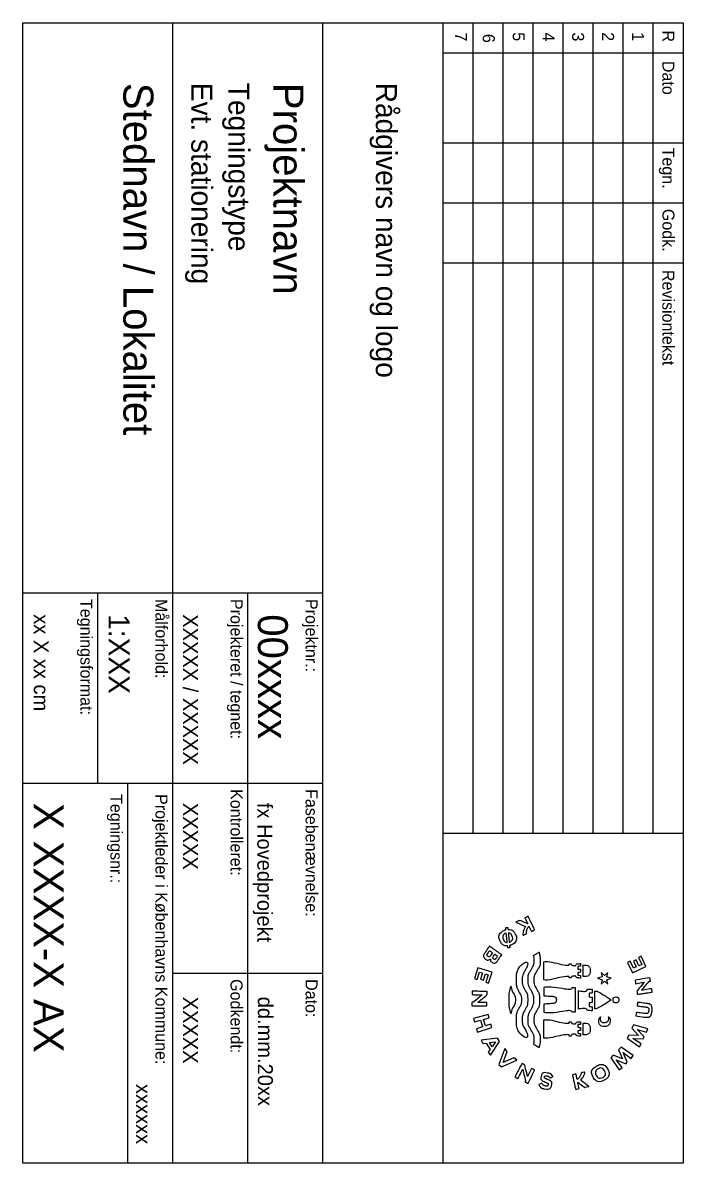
# Model space of a CAD drawing. Extents: x 1 to 12, y 1 to 20.
import ezdxf

# ---------------------------------------------------------------- set-up
doc = ezdxf.new("R2010")
doc.units = 0
doc.layers.add('Tegningshoved', color=7, linetype='Continuous')

msp = doc.modelspace()

# ---------------------------------------------------------------- linework, layer by layer
at = {"layer": 'Tegningshoved'}
for p, q in [((1, 0.999), (1, 19.999)), ((1, 19.999), (12, 19.999)), ((3.5, 0.999), (3.5, 19.999)), ((6, 0.999), (6, 19.999)), ((8, 0.999), (8, 19.999)), ((8.5, 6.499), (8.5, 19.999)), ((9, 6.499), (9, 19.999)), ((9.5, 6.499), (9.5, 19.999)), ((10, 6.499), (10, 19.999)), ((10.5, 6.499), (10.5, 19.999)), ((11, 6.499), (11, 19.999)), ((11.5, 6.499), (11.5, 19.999)), ((12, 19.999), (12, 0.999)), ((8, 19.499), (12, 19.499)), ((8, 17.999), (12, 17.999)), ((8, 16.999), (12, 16.999)), ((8, 15.999), (12, 15.999)), ((1, 10.499), (6, 10.499)), ((2.25, 7.332), (2.25, 10.499)), ((4.75, 0.999), (4.75, 10.499)), ((1, 7.332), (6, 7.332)), ((2.75, 0.999), (2.75, 7.332)), ((8, 6.499), (12, 6.499)), ((3.5, 4.166), (6, 4.166)), ((12, 0.999), (1, 0.999))]:
    msp.add_line(p, q, dxfattribs=at)
for points in [[(11.38, 4.278), (11.3, 4.449), (11.255, 4.428), (11.31, 4.311), (11.263, 4.289), (11.217, 4.386), (11.172, 4.365), (11.218, 4.268), (11.174, 4.247), (11.119, 4.363), (11.074, 4.342), (11.155, 4.172)], [(8.578, 4.255), (8.522, 4.076), (8.569, 4.061), (8.607, 4.184), (8.657, 4.168), (8.625, 4.065), (8.672, 4.051), (8.705, 4.153), (8.751, 4.139), (8.712, 4.016), (8.759, 4.001), (8.816, 4.18)], [(10.729, 4.102), (10.746, 4.178), (10.689, 4.125), (10.632, 4.178), (10.649, 4.102), (10.575, 4.079), (10.649, 4.056), (10.632, 3.98), (10.689, 4.033), (10.746, 3.98), (10.729, 4.056), (10.803, 4.079)], [(8.559, 3.24), (8.576, 3.182), (8.814, 3.257), (8.797, 3.313), (8.705, 3.285), (8.673, 3.394), (8.766, 3.42), (8.749, 3.477), (8.509, 3.41), (8.526, 3.352), (8.626, 3.38), (8.658, 3.271)], [(11.171, 3.303), (11.146, 3.25), (11.258, 3.126), (11.092, 3.133), (11.067, 3.08), (11.27, 2.937), (11.3, 2.988), (11.164, 3.079), (11.335, 3.071), (11.35, 3.104), (11.233, 3.229), (11.391, 3.184), (11.411, 3.239)], [(8.754, 2.849), (8.792, 2.799), (8.938, 3.027), (8.905, 3.08), (8.636, 3.046), (8.664, 2.992), (8.72, 3.001), (8.785, 2.895)], [(8.773, 3.009), (8.872, 3.023), (8.816, 2.94)], [(8.928, 2.645), (8.974, 2.602), (9.23, 2.717), (9.18, 2.756), (8.999, 2.675), (9.07, 2.86), (9.028, 2.908)], [(10.965, 2.932), (10.924, 2.89), (10.988, 2.735), (10.834, 2.798), (10.793, 2.756), (10.936, 2.553), (10.981, 2.591), (10.883, 2.722), (11.042, 2.657), (11.067, 2.684), (10.999, 2.841), (11.132, 2.746), (11.169, 2.791)]]:
    msp.add_lwpolyline(points, close=True, dxfattribs=at)
for points, degree in [([(9.417, 5.112), (9.417, 5.112), (9.363, 5.086), (9.363, 5.086), (9.363, 5.086), (9.411, 4.987), (9.411, 4.987), (9.411, 4.987), (9.279, 5.045), (9.279, 5.045), (9.279, 5.045), (9.213, 5.013), (9.213, 5.013), (9.213, 5.013), (9.374, 4.943), (9.374, 4.943), (9.35, 4.904), (9.328, 4.841), (9.332, 4.794), (9.332, 4.794), (9.389, 4.821), (9.389, 4.821), (9.388, 4.861), (9.406, 4.914), (9.43, 4.948), (9.43, 4.948), (9.472, 4.861), (9.472, 4.861), (9.472, 4.861), (9.525, 4.887), (9.525, 4.887)], 3), ([(9.525, 4.887), (9.525, 4.887), (9.417, 5.112), (9.417, 5.112)], 2), ([(9.079, 4.586), (9.079, 4.586), (9.112, 4.589), (9.112, 4.589), (9.112, 4.589), (9.109, 4.624), (9.109, 4.624), (9.12, 4.627), (9.131, 4.631), (9.142, 4.637), (9.208, 4.673), (9.236, 4.752), (9.199, 4.822), (9.173, 4.868), (9.128, 4.892), (9.081, 4.892), (9.081, 4.892), (9.077, 4.928), (9.077, 4.928), (9.077, 4.928), (9.044, 4.923), (9.044, 4.923), (9.044, 4.923), (9.048, 4.888), (9.048, 4.888), (9.036, 4.885), (9.024, 4.88), (9.013, 4.874), (8.947, 4.838), (8.918, 4.759), (8.956, 4.69), (8.981, 4.643), (9.028, 4.619), (9.075, 4.62), (9.075, 4.62), (9.079, 4.586), (9.079, 4.586)], 3), ([(9.007, 4.718), (8.986, 4.758), (9.001, 4.806), (9.039, 4.827), (9.044, 4.829), (9.048, 4.831), (9.053, 4.833), (9.053, 4.833), (9.07, 4.676), (9.07, 4.676), (9.044, 4.678), (9.021, 4.693), (9.007, 4.718)], 3), ([(9.148, 4.794), (9.169, 4.754), (9.154, 4.706), (9.116, 4.685), (9.112, 4.683), (9.107, 4.681), (9.103, 4.68), (9.103, 4.68), (9.087, 4.836), (9.087, 4.836), (9.111, 4.833), (9.135, 4.818), (9.148, 4.794)], 3), ([(8.771, 4.613), (8.771, 4.613), (8.707, 4.519), (8.707, 4.519), (8.666, 4.459), (8.679, 4.42), (8.712, 4.397), (8.737, 4.38), (8.764, 4.382), (8.79, 4.405), (8.787, 4.38), (8.796, 4.36), (8.815, 4.348), (8.847, 4.326), (8.881, 4.332), (8.921, 4.391), (8.921, 4.391), (8.977, 4.473), (8.977, 4.473)], 3), ([(8.977, 4.473), (8.977, 4.473), (8.771, 4.613), (8.771, 4.613)], 2), ([(8.775, 4.539), (8.775, 4.539), (8.824, 4.505), (8.824, 4.505), (8.824, 4.505), (8.793, 4.46), (8.793, 4.46), (8.778, 4.438), (8.761, 4.435), (8.748, 4.445), (8.732, 4.455), (8.729, 4.472), (8.744, 4.494)], 3), ([(8.744, 4.494), (8.744, 4.494), (8.775, 4.539), (8.775, 4.539)], 2), ([(8.86, 4.48), (8.86, 4.48), (8.906, 4.449), (8.906, 4.449), (8.906, 4.449), (8.884, 4.417), (8.884, 4.417), (8.87, 4.395), (8.855, 4.391), (8.841, 4.401), (8.825, 4.412), (8.826, 4.43), (8.838, 4.448)], 3), ([(8.838, 4.448), (8.838, 4.448), (8.86, 4.48), (8.86, 4.48)], 2), ([(9.618, 3.056), (9.618, 3.151), (9.581, 3.201), (9.557, 3.245), (9.535, 3.284), (9.514, 3.318), (9.514, 3.389), (9.514, 3.46), (9.535, 3.493), (9.557, 3.532), (9.581, 3.576), (9.608, 3.626), (9.609, 3.72), (9.608, 3.814), (9.581, 3.863), (9.557, 3.907), (9.535, 3.946), (9.514, 3.98), (9.514, 4.051), (9.514, 4.122), (9.535, 4.155), (9.557, 4.194), (9.581, 4.238), (9.618, 4.288), (9.618, 4.383), (9.618, 4.443), (9.599, 4.515), (9.599, 4.515), (9.599, 4.515), (9.509, 4.463), (9.509, 4.463), (9.509, 4.463), (9.517, 4.42), (9.517, 4.383), (9.517, 4.312), (9.496, 4.274), (9.475, 4.235), (9.45, 4.191), (9.417, 4.154), (9.417, 4.059), (9.417, 3.964), (9.447, 3.912), (9.472, 3.868), (9.493, 3.83), (9.512, 3.79), (9.512, 3.72), (9.512, 3.65), (9.493, 3.61), (9.472, 3.571), (9.447, 3.527), (9.417, 3.475), (9.417, 3.38), (9.417, 3.285), (9.45, 3.249), (9.475, 3.205), (9.496, 3.166), (9.517, 3.127), (9.517, 3.056), (9.517, 3.019), (9.509, 2.976), (9.509, 2.976), (9.509, 2.976), (9.599, 2.925), (9.599, 2.925), (9.599, 2.925), (9.618, 2.996), (9.618, 3.056)], 3), ([(9.354, 3.248), (9.333, 3.286), (9.319, 3.324), (9.319, 3.393), (9.319, 3.462), (9.335, 3.5), (9.356, 3.538), (9.379, 3.58), (9.409, 3.629), (9.41, 3.72), (9.409, 3.81), (9.379, 3.859), (9.356, 3.902), (9.335, 3.939), (9.319, 3.977), (9.319, 4.046), (9.319, 4.116), (9.333, 4.154), (9.354, 4.192), (9.378, 4.235), (9.416, 4.292), (9.406, 4.387), (9.22, 4.243), (9.223, 4.044), (9.223, 4.044), (9.223, 3.956), (9.24, 3.906), (9.264, 3.864), (9.285, 3.826), (9.31, 3.787), (9.311, 3.72), (9.31, 3.652), (9.285, 3.613), (9.264, 3.576), (9.24, 3.533), (9.223, 3.483), (9.223, 3.395), (9.223, 3.395), (9.22, 3.197), (9.406, 3.052), (9.416, 3.148), (9.378, 3.205), (9.354, 3.248)], 3), ([(10.099, 4.11), (10.099, 4.11), (10.099, 4.086), (10.099, 4.086), (10.099, 4.086), (10.134, 4.086), (10.134, 4.086), (10.134, 4.086), (10.14, 4.117), (10.173, 4.117), (10.173, 4.117), (10.173, 4.117), (10.173, 4.117), (10.173, 4.117), (10.204, 4.118), (10.204, 4.118), (10.204, 4.118), (10.228, 4.089), (10.228, 4.089), (10.228, 4.089), (10.291, 4.083), (10.291, 4.083), (10.291, 4.083), (10.291, 4.126), (10.291, 4.126), (10.291, 4.126), (10.246, 4.132), (10.246, 4.132), (10.246, 4.132), (10.246, 4.174), (10.246, 4.174), (10.246, 4.174), (10.291, 4.18), (10.291, 4.18), (10.291, 4.18), (10.291, 4.204), (10.291, 4.204), (10.291, 4.204), (10.291, 4.228), (10.291, 4.228), (10.291, 4.228), (10.246, 4.234), (10.246, 4.234), (10.246, 4.234), (10.246, 4.276), (10.246, 4.276), (10.246, 4.276), (10.291, 4.282), (10.291, 4.282), (10.291, 4.282), (10.291, 4.325), (10.291, 4.325), (10.291, 4.325), (10.228, 4.319), (10.228, 4.319), (10.228, 4.319), (10.204, 4.289), (10.204, 4.289), (10.204, 4.289), (10.173, 4.291), (10.173, 4.291), (10.173, 4.291), (10.173, 4.291), (10.173, 4.291), (10.14, 4.291), (10.134, 4.322), (10.134, 4.322), (10.134, 4.322), (10.099, 4.322), (10.099, 4.322), (10.099, 4.322), (10.099, 4.298), (10.099, 4.298), (9.979, 4.299), (9.807, 4.359), (9.677, 4.359), (9.677, 4.359), (9.677, 4.204), (9.677, 4.204), (9.677, 4.204), (9.677, 4.049), (9.677, 4.049), (9.807, 4.049), (9.979, 4.109), (10.099, 4.11)], 3), ([(10.333, 4.107), (10.333, 4.107), (10.353, 4.108), (10.353, 4.108), (10.413, 4.108), (10.45, 4.151), (10.45, 4.204), (10.45, 4.257), (10.413, 4.3), (10.353, 4.3), (10.353, 4.3), (10.333, 4.3), (10.333, 4.3), (10.333, 4.3), (10.333, 4.107), (10.333, 4.107)], 3), ([(11.484, 3.85), (11.484, 3.85), (11.474, 3.907), (11.474, 3.907), (11.474, 3.907), (11.307, 3.88), (11.307, 3.88), (11.307, 3.88), (11.419, 4.013), (11.419, 4.013), (11.428, 4.024), (11.438, 4.032), (11.447, 4.033), (11.447, 4.033), (11.453, 4.034), (11.453, 4.034), (11.453, 4.034), (11.443, 4.091), (11.443, 4.091), (11.443, 4.091), (11.198, 4.045), (11.198, 4.045), (11.198, 4.045), (11.208, 3.988), (11.208, 3.988), (11.208, 3.988), (11.356, 4.016), (11.356, 4.016), (11.356, 4.016), (11.229, 3.865), (11.229, 3.865), (11.229, 3.865), (11.238, 3.812), (11.238, 3.812)], 3), ([(8.484, 3.866), (8.484, 3.866), (8.483, 3.807), (8.483, 3.807), (8.483, 3.807), (8.653, 3.804), (8.653, 3.804), (8.653, 3.804), (8.518, 3.693), (8.518, 3.693), (8.508, 3.684), (8.496, 3.679), (8.487, 3.679), (8.487, 3.679), (8.481, 3.679), (8.481, 3.679), (8.481, 3.679), (8.48, 3.621), (8.48, 3.621), (8.48, 3.621), (8.73, 3.621), (8.73, 3.621), (8.73, 3.621), (8.731, 3.679), (8.731, 3.679), (8.731, 3.679), (8.579, 3.679), (8.579, 3.679), (8.579, 3.679), (8.732, 3.805), (8.732, 3.805), (8.732, 3.805), (8.733, 3.858), (8.733, 3.858)], 3), ([(8.733, 3.858), (8.733, 3.858), (8.484, 3.866), (8.484, 3.866)], 2), ([(9.205, 3.72), (9.205, 3.811), (9.137, 3.851), (9.137, 3.972), (9.123, 3.925), (9.1, 3.824), (9.1, 3.72), (9.1, 3.615), (9.123, 3.514), (9.137, 3.468), (9.137, 3.589), (9.205, 3.628), (9.205, 3.72)], 3), ([(10.207, 3.919), (10.207, 3.919), (10.147, 3.919), (10.147, 3.919), (10.147, 3.919), (10.136, 3.894), (10.108, 3.894), (10.053, 3.894), (9.835, 3.937), (9.677, 3.928), (9.677, 3.928), (9.677, 3.79), (9.677, 3.79), (9.677, 3.79), (9.827, 3.779), (9.827, 3.779), (9.865, 3.775), (9.887, 3.751), (9.887, 3.72), (9.887, 3.689), (9.865, 3.664), (9.827, 3.66), (9.827, 3.66), (9.677, 3.649), (9.677, 3.649), (9.677, 3.649), (9.677, 3.511), (9.677, 3.511), (9.835, 3.503), (10.053, 3.546), (10.108, 3.546), (10.136, 3.546), (10.147, 3.521), (10.147, 3.521), (10.147, 3.521), (10.207, 3.521), (10.207, 3.521)], 3), ([(10.207, 3.521), (10.207, 3.524), (10.207, 3.919), (10.207, 3.919)], 2), ([(10.255, 3.568), (10.255, 3.568), (10.329, 3.578), (10.354, 3.578), (10.39, 3.578), (10.404, 3.543), (10.404, 3.543), (10.404, 3.543), (10.483, 3.539), (10.483, 3.539), (10.483, 3.539), (10.483, 3.604), (10.483, 3.604), (10.483, 3.604), (10.433, 3.611), (10.433, 3.611), (10.433, 3.611), (10.433, 3.669), (10.433, 3.669), (10.433, 3.669), (10.483, 3.675), (10.483, 3.675), (10.483, 3.675), (10.483, 3.764), (10.483, 3.764), (10.483, 3.764), (10.433, 3.771), (10.433, 3.771), (10.433, 3.771), (10.433, 3.828), (10.433, 3.828), (10.433, 3.828), (10.483, 3.835), (10.483, 3.835), (10.483, 3.835), (10.483, 3.9), (10.483, 3.9), (10.483, 3.9), (10.404, 3.896), (10.404, 3.896), (10.404, 3.896), (10.39, 3.862), (10.354, 3.862), (10.329, 3.862), (10.255, 3.871), (10.255, 3.871), (10.255, 3.871), (10.255, 3.568), (10.255, 3.568)], 3), ([(10.544, 3.573), (10.578, 3.573), (10.802, 3.72), (10.802, 3.72), (10.802, 3.72), (10.578, 3.866), (10.544, 3.866), (10.544, 3.866), (10.544, 3.866), (10.544, 3.866), (10.544, 3.866), (10.53, 3.866), (10.53, 3.866), (10.53, 3.866), (10.53, 3.573), (10.53, 3.573), (10.53, 3.573), (10.544, 3.573), (10.544, 3.573)], 3), ([(11.238, 3.812), (11.238, 3.812), (11.484, 3.85), (11.484, 3.85)], 2), ([(10.88, 3.671), (10.906, 3.671), (10.928, 3.693), (10.928, 3.72), (10.928, 3.747), (10.906, 3.768), (10.88, 3.768), (10.853, 3.768), (10.831, 3.747), (10.831, 3.72), (10.831, 3.693), (10.853, 3.671), (10.88, 3.671)], 3), ([(11.481, 3.533), (11.491, 3.608), (11.451, 3.654), (11.382, 3.662), (11.382, 3.662), (11.24, 3.679), (11.24, 3.679), (11.24, 3.679), (11.233, 3.62), (11.233, 3.62), (11.233, 3.62), (11.363, 3.603), (11.363, 3.603), (11.406, 3.598), (11.432, 3.582), (11.427, 3.54), (11.422, 3.499), (11.393, 3.489), (11.35, 3.495), (11.35, 3.495), (11.22, 3.511), (11.22, 3.511), (11.22, 3.511), (11.211, 3.452), (11.211, 3.452), (11.211, 3.452), (11.355, 3.433), (11.355, 3.433)], 3), ([(10.544, 3.573), (10.544, 3.573), (10.544, 3.573), (10.544, 3.573)], 2), ([(10.784, 3.366), (10.786, 3.393), (10.777, 3.417), (10.76, 3.435), (10.759, 3.436), (10.757, 3.435), (10.758, 3.434), (10.761, 3.422), (10.762, 3.41), (10.758, 3.397), (10.752, 3.37), (10.729, 3.348), (10.701, 3.344), (10.657, 3.336), (10.618, 3.371), (10.618, 3.414), (10.618, 3.421), (10.619, 3.427), (10.621, 3.434), (10.621, 3.435), (10.619, 3.436), (10.618, 3.435), (10.603, 3.418), (10.594, 3.396), (10.594, 3.372), (10.594, 3.318), (10.639, 3.274), (10.694, 3.277), (10.742, 3.279), (10.782, 3.318), (10.784, 3.366)], 3), ([(11.355, 3.433), (11.422, 3.425), (11.472, 3.459), (11.481, 3.533)], 2), ([(10.099, 3.141), (10.099, 3.141), (10.099, 3.117), (10.099, 3.117), (10.099, 3.117), (10.134, 3.117), (10.134, 3.117), (10.134, 3.117), (10.14, 3.148), (10.173, 3.148), (10.173, 3.148), (10.173, 3.148), (10.173, 3.148), (10.173, 3.148), (10.204, 3.15), (10.204, 3.15), (10.204, 3.15), (10.228, 3.12), (10.228, 3.12), (10.228, 3.12), (10.291, 3.114), (10.291, 3.114), (10.291, 3.114), (10.291, 3.158), (10.291, 3.158), (10.291, 3.158), (10.246, 3.163), (10.246, 3.163), (10.246, 3.163), (10.246, 3.205), (10.246, 3.205), (10.246, 3.205), (10.291, 3.211), (10.291, 3.211), (10.291, 3.211), (10.291, 3.235), (10.291, 3.235), (10.291, 3.235), (10.291, 3.259), (10.291, 3.259), (10.291, 3.259), (10.246, 3.265), (10.246, 3.265), (10.246, 3.265), (10.246, 3.307), (10.246, 3.307), (10.246, 3.307), (10.291, 3.313), (10.291, 3.313), (10.291, 3.313), (10.291, 3.356), (10.291, 3.356), (10.291, 3.356), (10.228, 3.351), (10.228, 3.351), (10.228, 3.351), (10.204, 3.321), (10.204, 3.321), (10.204, 3.321), (10.173, 3.323), (10.173, 3.323), (10.173, 3.323), (10.173, 3.323), (10.173, 3.323), (10.14, 3.323), (10.134, 3.354), (10.134, 3.354), (10.134, 3.354), (10.099, 3.354), (10.099, 3.354), (10.099, 3.354), (10.099, 3.33), (10.099, 3.33), (9.979, 3.331), (9.807, 3.39), (9.677, 3.39), (9.677, 3.39), (9.677, 3.235), (9.677, 3.235), (9.677, 3.235), (9.677, 3.081), (9.677, 3.081), (9.807, 3.081), (9.979, 3.14), (10.099, 3.141)], 3), ([(10.333, 3.139), (10.333, 3.139), (10.353, 3.139), (10.353, 3.139), (10.413, 3.139), (10.45, 3.183), (10.45, 3.235), (10.45, 3.288), (10.413, 3.332), (10.353, 3.332), (10.353, 3.332), (10.333, 3.332), (10.333, 3.332), (10.333, 3.332), (10.333, 3.139), (10.333, 3.139)], 3), ([(9.198, 2.438), (9.198, 2.438), (9.25, 2.411), (9.25, 2.411), (9.25, 2.411), (9.328, 2.562), (9.328, 2.562), (9.328, 2.562), (9.368, 2.393), (9.368, 2.393), (9.372, 2.38), (9.372, 2.367), (9.368, 2.359), (9.368, 2.359), (9.365, 2.354), (9.365, 2.354), (9.365, 2.354), (9.417, 2.328), (9.417, 2.328), (9.417, 2.328), (9.525, 2.552), (9.525, 2.552), (9.525, 2.552), (9.473, 2.578), (9.473, 2.578), (9.473, 2.578), (9.408, 2.442), (9.408, 2.442), (9.408, 2.442), (9.361, 2.634), (9.361, 2.634), (9.361, 2.634), (9.314, 2.659), (9.314, 2.659)], 3), ([(9.314, 2.659), (9.314, 2.659), (9.198, 2.438), (9.198, 2.438)], 2), ([(9.692, 2.237), (9.746, 2.226), (9.796, 2.243), (9.807, 2.299), (9.818, 2.354), (9.779, 2.379), (9.731, 2.397), (9.704, 2.407), (9.686, 2.42), (9.69, 2.438), (9.692, 2.452), (9.707, 2.458), (9.731, 2.453), (9.754, 2.448), (9.771, 2.436), (9.783, 2.417), (9.783, 2.417), (9.83, 2.443), (9.83, 2.443), (9.809, 2.477), (9.782, 2.493), (9.742, 2.501), (9.684, 2.513), (9.642, 2.491), (9.633, 2.445), (9.622, 2.393), (9.662, 2.366), (9.706, 2.349), (9.73, 2.339), (9.754, 2.326), (9.75, 2.305), (9.746, 2.287), (9.728, 2.281), (9.704, 2.286), (9.677, 2.291), (9.659, 2.307), (9.644, 2.334), (9.644, 2.334), (9.595, 2.306), (9.595, 2.306)], 3), ([(10.208, 2.23), (10.208, 2.23), (10.266, 2.242), (10.266, 2.242), (10.266, 2.242), (10.243, 2.35), (10.243, 2.35), (10.243, 2.35), (10.358, 2.262), (10.358, 2.262), (10.358, 2.262), (10.43, 2.278), (10.43, 2.278), (10.43, 2.278), (10.29, 2.384), (10.29, 2.384), (10.322, 2.416), (10.358, 2.472), (10.365, 2.519), (10.365, 2.519), (10.304, 2.506), (10.304, 2.506), (10.295, 2.467), (10.265, 2.42), (10.234, 2.392), (10.234, 2.392), (10.214, 2.486), (10.214, 2.486), (10.214, 2.486), (10.155, 2.473), (10.155, 2.473)], 3), ([(10.155, 2.473), (10.155, 2.473), (10.208, 2.23), (10.208, 2.23)], 2), ([(10.684, 2.38), (10.751, 2.415), (10.78, 2.494), (10.744, 2.564), (10.707, 2.633), (10.626, 2.654), (10.559, 2.619), (10.492, 2.584), (10.462, 2.505), (10.499, 2.435), (10.535, 2.366), (10.617, 2.345), (10.684, 2.38)], 3), ([(10.551, 2.462), (10.53, 2.503), (10.545, 2.551), (10.584, 2.571), (10.623, 2.591), (10.671, 2.577), (10.692, 2.537), (10.713, 2.496), (10.698, 2.448), (10.659, 2.428), (10.62, 2.408), (10.572, 2.422), (10.551, 2.462)], 3), ([(9.595, 2.306), (9.616, 2.269), (9.646, 2.246), (9.692, 2.237)], 2)]:
    msp.add_open_spline(points, degree=degree, dxfattribs=at)

# ---------------------------------------------------------------- texts
for s, height, p in [('7', 0.2, (8.2, 19.838)), ('6', 0.2, (8.661, 19.814)), ('5', 0.2, (9.161, 19.842)), ('4', 0.2, (9.661, 19.838)), ('3', 0.2, (10.15, 19.839)), ('2', 0.2, (10.65, 19.842)), ('1', 0.2, (11.15, 19.842)), ('R', 0.2, (11.654, 19.871)), ('Dato', 0.2, (11.654, 19.365)), ('Stednavn / Lokalitet         ', 0.5, (2.675, 18.999)), ('Evt. stationering                             ', 0.35, (3.807, 18.999)), ('Tegningstype          ', 0.35, (4.425, 18.999)), ('Projektnavn                   ', 0.5, (5.175, 18.999)), ('Rådgivers navn og logo', 0.35, (6.881, 19.001)), ('Tegn.', 0.2, (11.654, 17.92)), ('Godk.', 0.2, (11.654, 16.899)), ('Revisiontekst', 0.2, (11.654, 15.882)), ('Tegningsformat:', 0.2, (1.96, 10.399)), ('Målforhold:', 0.2, (3.21, 10.399)), ('Projekteret / tegnet:', 0.2, (4.46, 10.399)), ('Projektnr.:', 0.2, (5.71, 10.399)), ('xx X xx cm', 0.25, (1.183, 10.145)), ('1:XXX', 0.35, (2.428, 10.145)), ('XXXXX / XXXXX', 0.25, (3.668, 10.145)), ('00xxxx', 0.5, (4.915, 10.145)), ('Tegningsnr.:', 0.2, (2.46, 7.149)), ('Projektleder i Københavns Kommune:', 0.2, (3.21, 7.149)), ('Kontrolleret:', 0.2, (4.46, 7.232)), ('Fasebenævnelse:', 0.2, (5.71, 7.232)), ('X XXXX-X AX', 0.5, (1.183, 7.003)), ('XXXXX', 0.25, (3.668, 7.003)), ('fx Hovedprojekt', 0.25, (4.906, 7.003)), ('Godkendt:', 0.2, (4.46, 4.066)), ('Dato:', 0.2, (5.71, 4.066)), ('XXXXX', 0.25, (3.668, 3.773)), ('dd.mm.20xx', 0.25, (4.915, 3.773)), ('xxxxxx', 0.25, (2.883, 2.319))]:
    msp.add_text(s, height=height, rotation=270, dxfattribs=at).set_placement(p)

doc.saveas('drawing.dxf')
